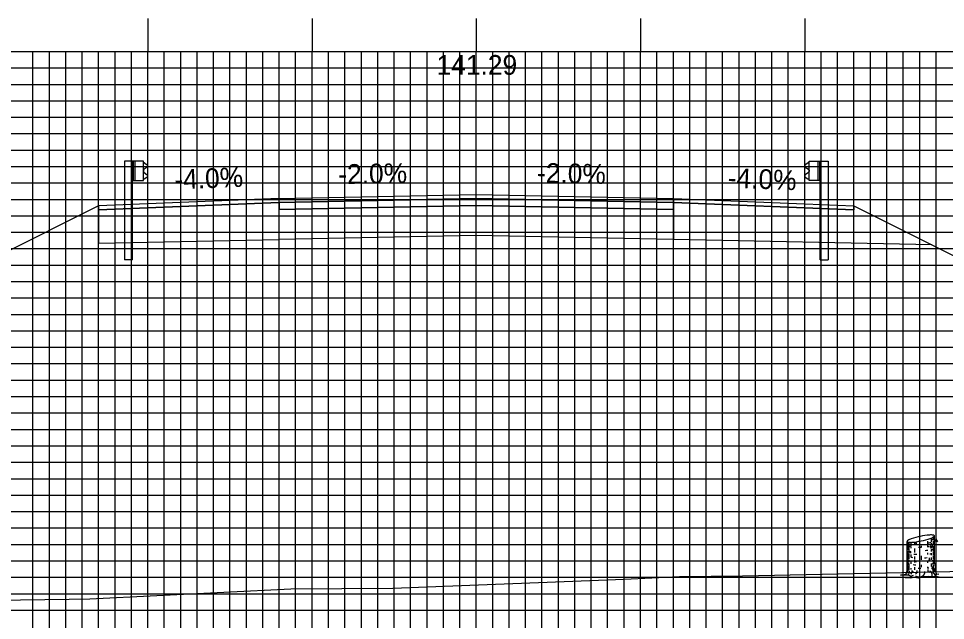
# Model space of a CAD drawing. Extents: x 1789730 to 1790074, y 442591 to 442811.
# Drawn here: x 1789868.3 to 1789924.8, y 442729 to 442765.7 of the extents above; entities that cross this region are included whole.
import ezdxf

# ---------------------------------------------------------------- set-up
doc = ezdxf.new("R2010")
doc.units = 0
for name, color, linetype in [('ANNOTATION', 7, 'Continuous'), ('D_Guardrail_Beam_Lt', 7, 'Continuous'), ('D_Guardrail_Beam_Rt', 7, 'Continuous'), ('D_Roadway_Centerline', 7, 'Continuous'), ('D_Roadway_Centerline_Text', 7, 'Continuous'), ('D_Roadway_Edge_Shoulder', 7, 'Continuous'), ('D_Roadway_Edge_TW', 7, 'Continuous'), ('D_Roadway_Pavement', 7, 'Continuous'), ('D_Roadway_SlopeLines', 7, 'Continuous'), ('D_Roadway_SubGrade', 7, 'Continuous'), ('M_Trees_Conifer_Pay', 7, 'Continuous'), ('MAJOR', 7, 'Continuous'), ('MINOR', 7, 'Continuous'), ('S_Roadway_Centerline', 7, 'Continuous')]:
    doc.layers.add(name, color=color, linetype=linetype)

msp = doc.modelspace()

# ---------------------------------------------------------------- linework, layer by layer
at = {"layer": 'ANNOTATION'}
msp.add_line((1789873.183, 442754.277), (1789823.441, 442729.407), dxfattribs=at)
at = {"layer": 'D_Guardrail_Beam_Lt'}
for p, q in [((1789874.754, 442756.981), (1789874.754, 442750.981)), ((1789875.224, 442756.981), (1789874.754, 442756.981)), ((1789875.912, 442756.981), (1789875.224, 442756.981)), ((1789875.224, 442756.981), (1789875.224, 442755.814)), ((1789875.287, 442756.981), (1789875.287, 442755.814)), ((1789875.391, 442756.981), (1789875.391, 442755.814)), ((1789875.912, 442755.814), (1789875.912, 442756.981)), ((1789875.912, 442756.897), (1789875.986, 442756.883)), ((1789876.145, 442756.633), (1789875.95, 442756.497)), ((1789876.002, 442756.876), (1789876.145, 442756.776)), ((1789875.916, 442756.433), (1789875.916, 442756.362)), ((1789875.95, 442756.298), (1789876.145, 442756.162)), ((1789875.224, 442755.814), (1789875.912, 442755.814)), ((1789875.245, 442750.981), (1789875.245, 442755.814)), ((1789875.986, 442755.912), (1789875.912, 442755.897)), ((1789876.145, 442756.019), (1789876.002, 442755.919)), ((1789875.245, 442750.981), (1789874.754, 442750.981))]:
    msp.add_line(p, q, dxfattribs=at)
for centre, major_axis, start_param, end_param in [((1789875.978, 442756.842), (0.0417, 0), 0.959931, 1.376053), ((1789876.095, 442756.705), (0.0877, 0), 5.323254, 7.243116), ((1789875.995, 442756.433), (-0.0789, 0), 5.323254, 6.283185), ((1789875.995, 442756.362), (-0.0789, 0), 6.283185, 7.243116), ((1789876.095, 442756.09), (0.0877, 0), 5.323254, 7.243116), ((1789875.978, 442755.953), (0.0417, 0), 4.907132, 5.323254)]:
    msp.add_ellipse(centre, major_axis=major_axis, ratio=0.995501, start_param=start_param, end_param=end_param, dxfattribs=at)
at = {"layer": 'D_Guardrail_Beam_Rt'}
for p, q in [((1789916.364, 442756.876), (1789916.22, 442756.776)), ((1789916.22, 442756.633), (1789916.415, 442756.497)), ((1789916.454, 442756.897), (1789916.379, 442756.883)), ((1789916.454, 442756.981), (1789917.141, 442756.981)), ((1789916.454, 442755.814), (1789916.454, 442756.981)), ((1789916.974, 442756.981), (1789916.974, 442755.814)), ((1789917.079, 442756.981), (1789917.079, 442755.814)), ((1789917.141, 442756.981), (1789917.612, 442756.981)), ((1789917.141, 442756.981), (1789917.141, 442755.814)), ((1789917.612, 442756.981), (1789917.612, 442750.981)), ((1789916.415, 442756.298), (1789916.22, 442756.162)), ((1789916.449, 442756.433), (1789916.449, 442756.362)), ((1789916.22, 442756.019), (1789916.364, 442755.919)), ((1789916.379, 442755.912), (1789916.454, 442755.897)), ((1789917.141, 442755.814), (1789916.454, 442755.814)), ((1789917.12, 442750.981), (1789917.12, 442755.814)), ((1789917.12, 442750.981), (1789917.612, 442750.981))]:
    msp.add_line(p, q, dxfattribs=at)
for centre, major_axis, start_param, end_param in [((1789916.27, 442756.705), (-0.0877, 0), 5.323254, 7.243116), ((1789916.387, 442756.842), (-0.0417, 0), 4.907132, 5.323254), ((1789916.27, 442756.09), (-0.0877, 0), 5.323254, 7.243116), ((1789916.37, 442756.433), (0.0789, 0), 0, 0.959931), ((1789916.37, 442756.362), (0.0789, 0), 5.323254, 6.283185), ((1789916.387, 442755.953), (-0.0417, 0), 0.959931, 1.376053)]:
    msp.add_ellipse(centre, major_axis=major_axis, ratio=0.995501, start_param=start_param, end_param=end_param, dxfattribs=at)
at = {"layer": 'D_Roadway_Edge_Shoulder'}
for points in [[(1789884.183, 442754.717), (1789876.183, 442754.397), (1789876.183, 442754.397), (1789873.183, 442754.277), (1789873.183, 442754.027), (1789884.183, 442754.467)], [(1789908.183, 442754.717), (1789916.183, 442754.397), (1789916.183, 442754.397), (1789919.183, 442754.277), (1789919.183, 442754.027), (1789908.183, 442754.467)]]:
    msp.add_lwpolyline(points, close=True, dxfattribs=at)
at = {"layer": 'D_Roadway_Edge_TW'}
msp.add_lwpolyline([(1789884.183, 442754.467), (1789884.183, 442754.717), (1789896.183, 442754.957), (1789908.183, 442754.717), (1789908.183, 442754.467), (1789896.183, 442754.707)], close=True, dxfattribs=at)
at = {"layer": 'D_Roadway_Pavement'}
msp.add_lwpolyline([(1789884.183, 442754.051), (1789884.183, 442754.467), (1789896.183, 442754.707), (1789908.183, 442754.467), (1789908.183, 442754.051), (1789896.183, 442754.291)], close=True, dxfattribs=at)
for points in [[(1789884.183, 442754.467), (1789884.183, 442754.051)], [(1789908.183, 442754.467), (1789908.183, 442754.051)]]:
    msp.add_lwpolyline(points, dxfattribs=at)
at = {"layer": 'D_Roadway_SlopeLines'}
msp.add_lwpolyline([(1789919.183, 442754.277), (1789956.118, 442735.81)], dxfattribs=at)
at = {"layer": 'D_Roadway_SubGrade'}
for points in [[(1789884.183, 442754.051), (1789884.183, 442754.467), (1789873.183, 442754.027), (1789873.183, 442754.277), (1789873.183, 442751.997), (1789884.183, 442752.217)], [(1789884.183, 442752.217), (1789884.183, 442754.467), (1789884.183, 442754.051), (1789896.183, 442754.291), (1789908.183, 442754.051), (1789908.183, 442754.467), (1789908.183, 442752.217), (1789896.183, 442752.457)], [(1789908.183, 442754.051), (1789908.183, 442754.467), (1789919.183, 442754.027), (1789919.183, 442754.277), (1789923.933, 442751.902), (1789908.183, 442752.217)]]:
    msp.add_lwpolyline(points, close=True, dxfattribs=at)
at = {"layer": 'M_Trees_Conifer_Pay'}
for p, q in [((1789923.892, 442734.049), (1789923.892, 442733.826)), ((1789924.01, 442734.11), (1789924.01, 442733.948)), ((1789924.081, 442732.536), (1789924.081, 442734.183)), ((1789922.417, 442732.125), (1789922.417, 442733.847)), ((1789922.465, 442733.81), (1789922.465, 442733.339)), ((1789922.523, 442733.799), (1789922.523, 442733.701)), ((1789922.523, 442733.627), (1789922.523, 442733.423)), ((1789922.648, 442733.791), (1789922.648, 442733.559)), ((1789922.648, 442733.518), (1789922.648, 442733.444)), ((1789922.868, 442733.811), (1789922.868, 442733.643)), ((1789923.274, 442733.58), (1789923.274, 442733.484)), ((1789923.664, 442733.853), (1789923.664, 442733.654)), ((1789923.664, 442733.596), (1789923.664, 442733.507)), ((1789923.892, 442733.738), (1789923.892, 442733.69)), ((1789923.95, 442733.555), (1789923.898, 442733.495)), ((1789924.01, 442733.88), (1789924.01, 442733.752)), ((1789924.01, 442733.565), (1789924.01, 442733.229)), ((1789922.465, 442733.274), (1789922.465, 442732.966)), ((1789922.465, 442732.919), (1789922.465, 442732.427)), ((1789922.523, 442733.365), (1789922.523, 442733.165)), ((1789922.523, 442733.118), (1789922.523, 442732.782)), ((1789922.648, 442733.04), (1789922.648, 442732.902)), ((1789922.868, 442733.406), (1789922.868, 442733.169)), ((1789922.868, 442732.925), (1789922.868, 442732.772)), ((1789923.274, 442732.966), (1789923.274, 442732.892)), ((1789923.664, 442733.16), (1789923.664, 442733.055)), ((1789923.892, 442733.355), (1789923.892, 442733.223)), ((1789923.892, 442733.112), (1789923.892, 442733.003)), ((1789924.01, 442733.192), (1789924.01, 442733.03)), ((1789924.01, 442732.982), (1789924.01, 442732.766)), ((1789922.465, 442732.373), (1789922.465, 442732.125)), ((1789922.523, 442732.729), (1789922.523, 442732.593)), ((1789922.523, 442732.494), (1789922.523, 442732.116)), ((1789922.648, 442732.63), (1789922.648, 442732.488)), ((1789922.868, 442732.729), (1789922.868, 442732.556)), ((1789923.274, 442732.867), (1789923.274, 442732.719)), ((1789923.274, 442732.427), (1789923.274, 442732.274)), ((1789923.664, 442732.688), (1789923.664, 442732.541)), ((1789923.892, 442732.867), (1789923.892, 442732.725)), ((1789923.892, 442732.498), (1789923.892, 442732.326)), ((1789924.01, 442732.735), (1789924.01, 442732.661)), ((1789924.01, 442732.62), (1789924.01, 442732.447)), ((1789922.648, 442732.226), (1789922.648, 442732.132)), ((1789922.648, 442731.732), (1789922.811, 442731.796)), ((1789922.868, 442732.278), (1789922.868, 442732.125)), ((1789923.664, 442732.309), (1789923.664, 442732.221)), ((1789923.085, 442731.668), (1789922.959, 442731.732))]:
    msp.add_line(p, q, dxfattribs=at)
for points in [[(1789923.865, 442733.643), (1789923.834, 442733.559), (1789923.83, 442733.491), (1789923.861, 442733.427)], [(1789923.898, 442733.681), (1789923.935, 442733.606), (1789923.982, 442733.663), (1789924.04, 442733.732), (1789924.133, 442733.925), (1789924.197, 442733.973), (1789924.228, 442733.979)], [(1789923.913, 442733.427), (1789923.95, 442733.555), (1789924.013, 442733.67), (1789924.044, 442733.738), (1789924.113, 442733.884)], [(1789924.127, 442733.913), (1789924.203, 442733.921), (1789924.275, 442733.822)], [(1789922.596, 442733.153), (1789922.591, 442733.248), (1789922.634, 442733.225), (1789922.634, 442733.131)], [(1789924.081, 442732.536), (1789924.133, 442732.274), (1789924.149, 442732), (1789924.207, 442731.875), (1789924.343, 442731.844), (1789924.112, 442731.807), (1789924.112, 442731.807), (1789924.118, 442731.759), (1789924.366, 442731.665), (1789924.091, 442731.681), (1789923.736, 442731.702), (1789923.414, 442731.691), (1789923.421, 442731.774), (1789923.272, 442731.691), (1789923.085, 442731.668), (1789923.11, 442731.601), (1789922.842, 442731.644), (1789922.621, 442731.617), (1789922.329, 442731.634), (1789922.617, 442731.691), (1789922.648, 442731.732), (1789922.486, 442731.79), (1789922.249, 442731.801), (1789922.008, 442731.801), (1789922.35, 442731.858), (1789922.391, 442731.938), (1789922.417, 442732.125)], [(1789923.736, 442732.754), (1789923.748, 442732.677), (1789923.795, 442732.688), (1789923.783, 442732.854)], [(1789924.007, 442732.393), (1789924.013, 442732.247), (1789924.06, 442732.179), (1789924.071, 442731.98)], [(1789922.465, 442732.078), (1789922.444, 442732), (1789922.424, 442731.906)], [(1789922.543, 442732.058), (1789922.549, 442731.942), (1789922.496, 442731.854), (1789922.486, 442731.79)], [(1789922.706, 442732.085), (1789922.706, 442731.953), (1789922.617, 442731.854)], [(1789922.932, 442731.844), (1789923, 442731.938), (1789923.027, 442732.078)], [(1789923.421, 442731.774), (1789923.495, 442731.915), (1789923.505, 442732.017)], [(1789923.671, 442732.142), (1789923.682, 442732.017), (1789923.756, 442731.973)], [(1789923.95, 442731.753), (1789923.935, 442731.891), (1789923.861, 442732.02)], [(1789923.908, 442732.247), (1789923.982, 442732.142), (1789923.987, 442731.969), (1789924.112, 442731.807)]]:
    msp.add_lwpolyline(points, dxfattribs=at)
for centre, radius, start, end in [((1789924.273, 442729.08), 5.179, 101.7194, 108.0594), ((1789924.273, 442729.08), 5.179, 95.3794, 101.7194), ((1789922.226, 442738.95), 5.179, 281.7194, 288.0594), ((1789923.863, 442733.438), 0.802, 79.2194, 95.3794), ((1789923.583, 442734.788), 0.802, 288.0594, 304.2194), ((1789923.966, 442733.979), 0.251, 71.0501, 79.2194), ((1789923.893, 442734.333), 0.251, 304.2194, 312.3887), ((1789923.95, 442734.151), 0.172, 300, 311.2506), ((1789924.021, 442734.139), 0.0817, 56.7194, 71.0501), ((1789924.006, 442734.208), 0.0817, 312.3887, 326.7194), ((1789924.022, 442734.068), 0.0624, 311.2506, 330), ((1789924.037, 442734.163), 0.0527, 46.923, 56.7194), ((1789924.051, 442734.178), 0.0314, 34.2194, 46.923), ((1789924.031, 442734.192), 0.0527, 326.7194, 336.5158), ((1789924.038, 442734.059), 0.0441, 330, 343.9485), ((1789924.055, 442734.181), 0.0264, 23.4074, 34.2194), ((1789924.05, 442734.184), 0.0314, 336.5158, 349.2194), ((1789924.059, 442734.183), 0.0226, 11.7194, 23.4074), ((1789924.048, 442734.056), 0.0334, 343.9485, 354.2151), ((1789924.059, 442734.183), 0.0226, 0.0315, 11.7194), ((1789924.055, 442734.183), 0.0264, 349.2194, 0.0315), ((1789922.45, 442733.669), 0.0334, 163.9485, 180), ((1789922.45, 442733.669), 0.0334, 180, 196.0515), ((1789922.444, 442733.847), 0.0264, 169.2194, 180.0315), ((1789922.44, 442733.847), 0.0226, 180.0315, 191.7194), ((1789922.46, 442733.672), 0.0441, 196.0515, 210), ((1789922.449, 442733.846), 0.0314, 156.5158, 169.2194), ((1789922.44, 442733.847), 0.0226, 191.7194, 203.4074), ((1789922.444, 442733.848), 0.0264, 203.4074, 214.2194), ((1789922.468, 442733.838), 0.0527, 146.7194, 156.5158), ((1789922.448, 442733.851), 0.0314, 214.2194, 226.923), ((1789922.476, 442733.681), 0.0624, 210, 228.7494), ((1789922.493, 442733.822), 0.0817, 132.3887, 146.7194), ((1789922.462, 442733.867), 0.0527, 226.923, 236.7194), ((1789922.478, 442733.891), 0.0817, 236.7194, 251.0501), ((1789922.548, 442733.764), 0.172, 228.7494, 240), ((1789922.606, 442733.697), 0.251, 124.2194, 132.3887), ((1789922.533, 442734.051), 0.251, 251.0501, 259.2194), ((1789922.747, 442734.109), 0.571, 240, 240.3367), ((1789922.916, 442733.241), 0.802, 108.0594, 124.2194), ((1789922.636, 442734.592), 0.802, 259.2194, 275.3794), ((1789922.747, 442734.109), 0.571, 246.8597, 257.9846), ((1789922.226, 442738.95), 5.179, 275.3794, 281.7194), ((1789923.25, 442737.859), 4.124, 264.6955, 266.7331), ((1789923.248, 442737.626), 4.124, 268.0751, 270), ((1789923.248, 442737.626), 4.124, 270, 270.3581), ((1789923.248, 442737.626), 4.124, 275.7849, 277.0558), ((1789923.25, 442737.859), 4.124, 276.238, 278.1032), ((1789923.75, 442734.342), 0.571, 278.1032, 284.3667), ((1789923.75, 442734.496), 0.571, 284.4317, 292.4132), ((1789923.75, 442734.342), 0.571, 297.0237, 300), ((1789923.95, 442733.997), 0.172, 300, 311.2506), ((1789924.022, 442733.914), 0.0624, 311.2506, 330), ((1789924.038, 442733.905), 0.0441, 330, 343.9485), ((1789924.048, 442733.902), 0.0334, 343.9485, 354.2151), ((1789924.048, 442733.458), 0.0334, 343.9485, 354.2151), ((1789922.45, 442733.222), 0.0334, 163.9485, 180), ((1789922.45, 442733.222), 0.0334, 180, 196.0515), ((1789922.45, 442733.012), 0.0334, 163.9485, 180), ((1789922.45, 442733.012), 0.0334, 180, 196.0515), ((1789922.46, 442733.225), 0.0441, 196.0515, 210), ((1789922.46, 442733.015), 0.0441, 196.0515, 210), ((1789922.476, 442733.234), 0.0624, 210, 228.7494), ((1789922.476, 442733.024), 0.0624, 210, 228.7494), ((1789922.548, 442733.317), 0.172, 228.7494, 240), ((1789922.548, 442733.107), 0.172, 228.7494, 240), ((1789922.747, 442733.662), 0.571, 240, 240.3367), ((1789922.747, 442733.452), 0.571, 240, 246.8597), ((1789922.749, 442733.898), 0.571, 240, 247.0587), ((1789922.747, 442733.452), 0.571, 259.2707, 261.8968), ((1789923.248, 442736.969), 4.124, 261.8968, 263.1474), ((1789923.248, 442737.179), 4.124, 264.081, 266.6676), ((1789923.249, 442737.415), 4.124, 273.7052, 275.9504), ((1789923.248, 442737.179), 4.124, 277.6125, 278.1032), ((1789923.749, 442733.662), 0.571, 278.1032, 286.9296), ((1789923.75, 442733.898), 0.571, 284.4493, 297.0429), ((1789923.749, 442733.662), 0.571, 297.1896, 300), ((1789923.749, 442733.452), 0.571, 297.1896, 300), ((1789923.948, 442733.317), 0.172, 300, 311.2506), ((1789923.948, 442733.107), 0.172, 300, 311.2506), ((1789924.021, 442733.234), 0.0624, 311.2506, 330), ((1789924.021, 442733.024), 0.0624, 311.2506, 330), ((1789924.036, 442733.225), 0.0441, 330, 343.9485), ((1789924.036, 442733.015), 0.0441, 330, 343.9485), ((1789924.047, 442733.222), 0.0334, 343.9485, 354.2151), ((1789924.047, 442733.012), 0.0334, 343.9485, 354.2151), ((1789922.45, 442732.775), 0.0334, 163.9485, 180), ((1789922.45, 442732.775), 0.0334, 180, 196.0515), ((1789922.45, 442732.578), 0.0334, 163.9485, 180), ((1789922.45, 442732.382), 0.0334, 163.9485, 180), ((1789922.45, 442732.382), 0.0334, 180, 196.0515), ((1789922.46, 442732.778), 0.0441, 196.0515, 210), ((1789922.46, 442732.385), 0.0441, 196.0515, 210), ((1789922.476, 442732.787), 0.0624, 210, 228.7494), ((1789922.476, 442732.394), 0.0624, 210, 228.7494), ((1789922.548, 442732.87), 0.172, 228.7494, 240), ((1789922.548, 442732.477), 0.172, 228.7494, 240), ((1789922.747, 442733.215), 0.571, 240, 246.8597), ((1789922.737, 442733.024), 0.571, 241.2369, 248.0268), ((1789922.747, 442732.822), 0.571, 240, 246.8597), ((1789923.248, 442736.535), 4.124, 263.4991, 265.8397), ((1789923.248, 442736.733), 4.124, 264.716, 266.3193), ((1789923.248, 442736.969), 4.124, 270, 270.3581), ((1789923.248, 442736.969), 4.124, 273.1493, 275.4569), ((1789923.749, 442733.215), 0.571, 285.3983, 297.1896), ((1789923.749, 442733.017), 0.571, 289.2907, 300), ((1789923.948, 442732.672), 0.172, 300, 311.2506), ((1789924.021, 442732.59), 0.0624, 311.2506, 330), ((1789924.036, 442732.581), 0.0441, 330, 343.9485), ((1789924.047, 442732.578), 0.0334, 343.9485, 354.2151), ((1789922.45, 442732.162), 0.0334, 163.9485, 180), ((1789922.45, 442732.162), 0.0334, 180, 196.0515), ((1789922.46, 442732.165), 0.0441, 196.0515, 210), ((1789922.476, 442732.174), 0.0624, 210, 228.7494), ((1789922.548, 442732.257), 0.172, 228.7494, 240), ((1789922.747, 442732.602), 0.571, 240, 244.5314), ((1789923.248, 442736.119), 4.124, 262.4438, 263.512), ((1789923.248, 442736.339), 4.124, 267.8117, 270), ((1789923.248, 442736.339), 4.124, 270, 270.1328), ((1789923.248, 442736.339), 4.124, 275.7849, 276.7896), ((1789923.248, 442736.119), 4.124, 277.3684, 278.1032), ((1789923.749, 442732.602), 0.571, 278.1032, 281.637), ((1789923.749, 442732.822), 0.571, 288.5067, 297.2721), ((1789923.948, 442732.257), 0.172, 300, 311.2506), ((1789924.021, 442732.174), 0.0624, 311.2506, 330), ((1789924.036, 442732.165), 0.0441, 330, 343.9485), ((1789924.047, 442732.162), 0.0334, 343.9485, 354.2151)]:
    msp.add_arc(centre, radius, start, end, dxfattribs=at)
at = {"layer": 'MAJOR'}
for p, q in [((1789876.183, 442765.669), (1789876.183, 442763.665)), ((1789886.183, 442765.669), (1789886.183, 442763.665)), ((1789896.183, 442765.669), (1789896.183, 442763.665)), ((1789906.183, 442765.669), (1789906.183, 442763.665)), ((1789916.183, 442765.669), (1789916.183, 442763.665)), ((1789756.183, 442763.665), (1790036.183, 442763.665)), ((1789756.183, 442763.665), (1790036.183, 442763.665)), ((1789876.183, 442723.665), (1789876.183, 442763.665)), ((1789886.183, 442723.665), (1789886.183, 442763.665)), ((1789896.183, 442723.665), (1789896.183, 442763.665)), ((1789906.183, 442723.665), (1789906.183, 442763.665)), ((1789916.183, 442723.665), (1789916.183, 442763.665)), ((1789756.183, 442758.665), (1790036.183, 442758.665)), ((1789756.183, 442753.665), (1790036.183, 442753.665)), ((1789756.183, 442748.665), (1790036.183, 442748.665)), ((1789756.183, 442743.665), (1790036.183, 442743.665)), ((1789756.183, 442738.665), (1790036.183, 442738.665)), ((1789756.183, 442733.665), (1790036.183, 442733.665))]:
    msp.add_line(p, q, dxfattribs=at)
at = {"layer": 'MINOR'}
for p, q in [((1789869.183, 442723.665), (1789869.183, 442763.665)), ((1789870.183, 442723.665), (1789870.183, 442763.665)), ((1789871.183, 442723.665), (1789871.183, 442763.665)), ((1789872.183, 442723.665), (1789872.183, 442763.665)), ((1789873.183, 442723.665), (1789873.183, 442763.665)), ((1789874.183, 442723.665), (1789874.183, 442763.665)), ((1789875.183, 442723.665), (1789875.183, 442763.665)), ((1789877.183, 442723.665), (1789877.183, 442763.665)), ((1789878.183, 442723.665), (1789878.183, 442763.665)), ((1789879.183, 442723.665), (1789879.183, 442763.665)), ((1789880.183, 442723.665), (1789880.183, 442763.665)), ((1789881.183, 442723.665), (1789881.183, 442763.665)), ((1789882.183, 442723.665), (1789882.183, 442763.665)), ((1789883.183, 442723.665), (1789883.183, 442763.665)), ((1789884.183, 442723.665), (1789884.183, 442763.665)), ((1789885.183, 442723.665), (1789885.183, 442763.665)), ((1789887.183, 442723.665), (1789887.183, 442763.665)), ((1789888.183, 442723.665), (1789888.183, 442763.665)), ((1789889.183, 442723.665), (1789889.183, 442763.665)), ((1789890.183, 442723.665), (1789890.183, 442763.665)), ((1789891.183, 442723.665), (1789891.183, 442763.665)), ((1789892.183, 442723.665), (1789892.183, 442763.665)), ((1789893.183, 442723.665), (1789893.183, 442763.665)), ((1789894.183, 442723.665), (1789894.183, 442763.665)), ((1789895.183, 442723.665), (1789895.183, 442763.665)), ((1789897.183, 442723.665), (1789897.183, 442763.665)), ((1789898.183, 442723.665), (1789898.183, 442763.665)), ((1789899.183, 442723.665), (1789899.183, 442763.665)), ((1789900.183, 442723.665), (1789900.183, 442763.665)), ((1789901.183, 442723.665), (1789901.183, 442763.665)), ((1789902.183, 442723.665), (1789902.183, 442763.665)), ((1789903.183, 442723.665), (1789903.183, 442763.665)), ((1789904.183, 442723.665), (1789904.183, 442763.665)), ((1789905.183, 442723.665), (1789905.183, 442763.665)), ((1789907.183, 442723.665), (1789907.183, 442763.665)), ((1789908.183, 442723.665), (1789908.183, 442763.665)), ((1789909.183, 442723.665), (1789909.183, 442763.665)), ((1789910.183, 442723.665), (1789910.183, 442763.665)), ((1789911.183, 442723.665), (1789911.183, 442763.665)), ((1789912.183, 442723.665), (1789912.183, 442763.665)), ((1789913.183, 442723.665), (1789913.183, 442763.665)), ((1789914.183, 442723.665), (1789914.183, 442763.665)), ((1789915.183, 442723.665), (1789915.183, 442763.665)), ((1789917.183, 442723.665), (1789917.183, 442763.665)), ((1789918.183, 442723.665), (1789918.183, 442763.665)), ((1789919.183, 442723.665), (1789919.183, 442763.665)), ((1789920.183, 442723.665), (1789920.183, 442763.665)), ((1789921.183, 442723.665), (1789921.183, 442763.665)), ((1789922.183, 442723.665), (1789922.183, 442763.665)), ((1789923.183, 442723.665), (1789923.183, 442763.665)), ((1789924.183, 442723.665), (1789924.183, 442763.665)), ((1789756.183, 442762.665), (1790036.183, 442762.665)), ((1789756.183, 442761.665), (1790036.183, 442761.665)), ((1789756.183, 442760.665), (1790036.183, 442760.665)), ((1789756.183, 442759.665), (1790036.183, 442759.665)), ((1789756.183, 442757.665), (1790036.183, 442757.665)), ((1789756.183, 442756.665), (1790036.183, 442756.665)), ((1789756.183, 442755.665), (1790036.183, 442755.665)), ((1789756.183, 442754.665), (1790036.183, 442754.665)), ((1789756.183, 442752.665), (1790036.183, 442752.665)), ((1789756.183, 442751.665), (1790036.183, 442751.665)), ((1789756.183, 442750.665), (1790036.183, 442750.665)), ((1789756.183, 442749.665), (1790036.183, 442749.665)), ((1789756.183, 442747.665), (1790036.183, 442747.665)), ((1789756.183, 442746.665), (1790036.183, 442746.665)), ((1789756.183, 442745.665), (1790036.183, 442745.665)), ((1789756.183, 442744.665), (1790036.183, 442744.665)), ((1789756.183, 442742.665), (1790036.183, 442742.665)), ((1789756.183, 442741.665), (1790036.183, 442741.665)), ((1789756.183, 442740.665), (1790036.183, 442740.665)), ((1789756.183, 442739.665), (1790036.183, 442739.665)), ((1789756.183, 442737.665), (1790036.183, 442737.665)), ((1789756.183, 442736.665), (1790036.183, 442736.665)), ((1789756.183, 442735.665), (1790036.183, 442735.665)), ((1789756.183, 442734.665), (1790036.183, 442734.665)), ((1789756.183, 442732.665), (1790036.183, 442732.665)), ((1789756.183, 442731.665), (1790036.183, 442731.665)), ((1789756.183, 442730.665), (1790036.183, 442730.665)), ((1789756.183, 442729.665), (1790036.183, 442729.665))]:
    msp.add_line(p, q, dxfattribs=at)
at = {"layer": 'S_Roadway_Centerline'}
msp.add_lwpolyline([(1789855.114, 442730.106), (1789871.397, 442730.329), (1789872.648, 442730.357), (1789884.881, 442730.97), (1789891.102, 442731.002), (1789905.186, 442731.549), (1789908.557, 442731.71), (1789912.403, 442731.759), (1789927.921, 442732.078), (1789941.118, 442732.699), (1789944.737, 442732.872), (1789946.197, 442733.083), (1789949.045, 442734.261), (1789963.934, 442737.521), (1789967.671, 442738.049), (1789971.222, 442736.013)], dxfattribs=at)

# ---------------------------------------------------------------- texts
at = {"layer": 'ANNOTATION'}
for s, rotation, p in [('-4.0%', 2.2906, (1789877.815, 442755.264)), ('-2.0%', 1.1458, (1789887.789, 442755.59)), ('-2.0%', 358.8542, (1789899.869, 442755.684)), ('-4.0%', 357.7094, (1789911.474, 442755.387))]:
    msp.add_text(s, height=1.2, rotation=rotation, dxfattribs=at).set_placement(p)
at = {"layer": 'D_Roadway_Centerline'}
for s, p in [('C', (1789896.177, 442754.957)), ('L', (1789896.183, 442754.95))]:
    msp.add_text(s, height=0.0146, dxfattribs=at).set_placement(p)
at = {"layer": 'D_Roadway_Centerline_Text'}
msp.add_text('141.29', height=1.2, dxfattribs=at).set_placement((1789893.764, 442762.247))

doc.saveas('drawing.dxf')
